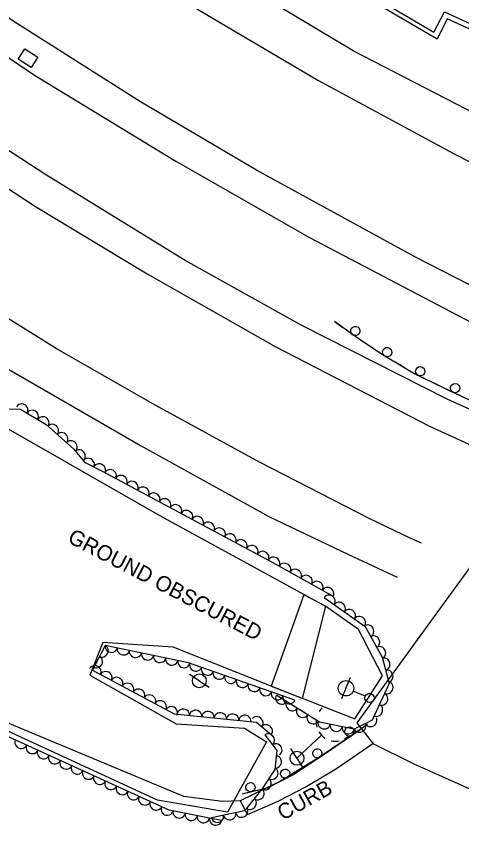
# Model space of a CAD drawing. Extents: x 1722896 to 1754269, y 648279 to 666297.
# Drawn here: x 1732619.2 to 1732763.3, y 649899.6 to 650161.6 of the extents above; entities that cross this region are included whole.
import ezdxf

# ---------------------------------------------------------------- set-up
doc = ezdxf.new("R2010")
doc.units = 0
for name, color, linetype in [('DESIGN - CENTERLINE - Proposed', 7, 'Continuous'), ('DESIGN - SCRATCH - User 1', 7, 'Continuous'), ('SURVEY - CENTERLINE - Preliminary', 7, 'Continuous'), ('SURVEY - CENTERLINE - Preliminary Text', 7, 'Continuous'), ('SURVEY - DRAINAGE - Natural Features', 7, 'Continuous'), ('SURVEY - DTM - Breaklines', 7, 'Continuous'), ('SURVEY - VEGETATION - Features with Text', 7, 'Continuous')]:
    doc.layers.add(name, color=color, linetype=linetype)

msp = doc.modelspace()

# ---------------------------------------------------------------- linework, layer by layer
at = {"layer": 'DESIGN - CENTERLINE - Proposed'}
msp.add_lwpolyline([(1732862.56, 650114.58), (1732871.81, 650112.14), (1732902.49, 650099), (1732911.38, 650094.61), (1732875.47, 650043.75), (1732812.6, 649955.84), (1732779.3, 649905.53), (1732747.93, 649919.55), (1732734.8, 649926.01), (1732729.4, 649932.93), (1732767.07, 649984.71), (1732812.61, 650049.09), (1732862.37, 650114.64)], dxfattribs=at)
at = {"layer": 'DESIGN - SCRATCH - User 1'}
for points in [[(1732834.68, 650126), (1732758.54, 650160.8), (1732755.35, 650154.19), (1732710.88, 650180.25), (1732670.33, 650204.01), (1732631.97, 650229.97), (1732581.97, 650266.2), (1732540.95, 650298.38), (1732462.37, 650368.7), (1732410.9, 650421.21), (1732341.07, 650504.92), (1732282.07, 650581.96), (1732214.97, 650674.59)], [(1732228.27, 650658.35), (1732269.62, 650601.48), (1732317.04, 650538.22), (1732364.61, 650478.14), (1732411.75, 650421.99), (1732463.83, 650368.65), (1732537.95, 650302.48), (1732586.89, 650264.11), (1732641.63, 650224.65), (1732675.82, 650201.62), (1732721.34, 650175.88), (1732754.2, 650156.42), (1732757.74, 650162.98), (1732807.66, 650139.97)], [(1732722.9, 650062.2), (1732722.08, 650062.78)], [(1732761.38, 650039.45), (1732747.6, 650046.14), (1732737.29, 650052.27), (1732729.73, 650057.27), (1732722.08, 650062.78)], [(1732724.8, 650060.82), (1732722.9, 650062.2)], [(1732729.83, 650057.2), (1732729.73, 650057.27), (1732726.1, 650059.89)], [(1732733.13, 650055.03), (1732731.17, 650056.32)], [(1732735.09, 650053.73), (1732733.13, 650055.03)], [(1732740.35, 650050.45), (1732737.29, 650052.27), (1732736.43, 650052.85)], [(1732743.75, 650048.43), (1732741.73, 650049.63)], [(1732745.77, 650047.23), (1732743.75, 650048.43)], [(1732751.26, 650044.36), (1732747.6, 650046.14), (1732747.14, 650046.41)], [(1732754.81, 650042.64), (1732752.7, 650043.66)], [(1732756.92, 650041.61), (1732754.81, 650042.64)], [(1732762.51, 650038.93), (1732761.38, 650039.45), (1732758.36, 650040.91)], [(1732777.47, 650032.08), (1732761.38, 650039.45)], [(1732732.83, 649932.49), (1732727.89, 649928.97), (1732718.79, 649922.75), (1732708.95, 649916.23), (1732700.34, 649911.85), (1732692.24, 649909.9)], [(1732729.61, 649930.2), (1732727.89, 649928.97), (1732725.84, 649927.57)], [(1732732.83, 649932.49), (1732730.91, 649931.12)], [(1732722.58, 649925.34), (1732720.64, 649924.01)], [(1732724.52, 649926.66), (1732722.58, 649925.34)], [(1732719.32, 649923.11), (1732718.79, 649922.75), (1732715.49, 649920.56)], [(1732714.15, 649919.68), (1732712.19, 649918.38)], [(1732712.19, 649918.38), (1732710.23, 649917.08)], [(1732708.9, 649916.2), (1732704.8, 649914.12)], [(1732701.28, 649912.33), (1732700.34, 649911.85), (1732699.08, 649911.55)], [(1732703.37, 649913.39), (1732701.28, 649912.33)], [(1732697.52, 649911.17), (1732693.05, 649910.1)]]:
    msp.add_lwpolyline(points, dxfattribs=at)
for centre, start, end in [((1732728.86, 650059.75), 347.4871, 347.4773), ((1732739.16, 650052.91), 352.4968, 352.4869), ((1732749.86, 650046.71), 357.3719, 357.3621), ((1732761.11, 650041.25), 357.3719, 357.3621), ((1732726.91, 649930.12), 57.637, 57.6272), ((1732716.59, 649923.09), 56.7664, 56.7566), ((1732706.19, 649916.51), 50.2371, 50.2273), ((1732694.95, 649912.1), 36.7851, 36.7753)]:
    msp.add_arc(centre, 1.5, start, end, dxfattribs=at)
at = {"layer": 'SURVEY - CENTERLINE - Preliminary'}
for points in [[(1732606.63, 650033.74), (1732665.91, 649999.81), (1732719.2, 649970.67), (1732711.67, 649940.84), (1732669.93, 649957.43), (1732647.19, 649958.96), (1732643.03, 649948.34), (1732670.93, 649932.64), (1732692.98, 649931.22), (1732700.1, 649926.85), (1732687.52, 649904), (1732664.85, 649907.92), (1732605.14, 649935.45)], [(1732701.67, 649944.83), (1732711.71, 649940.93), (1732728.7, 649934.26), (1732737.67, 649948.2), (1732729.86, 649963.14), (1732719.2, 649970.67), (1732712.16, 649974.42), (1732701.67, 649944.83)]]:
    msp.add_lwpolyline(points, dxfattribs=at)
at = {"layer": 'SURVEY - CENTERLINE - Preliminary Text'}
for points in [[(1732177.23, 650670.78), (1732207.28, 650628.76), (1732240.27, 650584.01), (1732277.17, 650534.26), (1732308.17, 650494.8), (1732347.59, 650447.31), (1732385.2, 650405.27), (1732423.32, 650365.2), (1732455.21, 650333.82), (1732493.46, 650299.04), (1732525.54, 650271.93), (1732567.3, 650239.43), (1732600.18, 650214.95), (1732636.27, 650190.54), (1732676.54, 650164.63), (1732716.69, 650140.93), (1732760.83, 650117.07), (1732799.05, 650097.55)], [(1732778.62, 650068.08), (1732748.36, 650083.69), (1732696.91, 650111.79), (1732659.43, 650133.9), (1732618.71, 650159.74), (1732569.4, 650193.82), (1732523.94, 650227.88), (1732487.08, 650258.27), (1732439.71, 650299.95), (1732393.89, 650344.9), (1732345.63, 650396.27), (1732315.87, 650430.1), (1732281.7, 650470.92), (1732248.95, 650512.82), (1732219.45, 650552.09), (1732190.79, 650591.17), (1732151.27, 650646.44)], [(1732143.79, 650639.34), (1732153.13, 650625.88), (1732193.64, 650569.45), (1732232.08, 650517.33), (1732271.5, 650466.99), (1732311.93, 650418.7), (1732362.13, 650362.86), (1732398.54, 650325.18), (1732431.93, 650292.77), (1732461.34, 650265.94), (1732489.99, 650242.08), (1732529.79, 650210.06), (1732579.85, 650173.43), (1732625.15, 650142.57), (1732670.82, 650114.68), (1732714.02, 650089.97), (1732772.83, 650059.19)], [(1732758.57, 650037.66), (1732711.61, 650061.49), (1732673.88, 650082.51), (1732628.45, 650110.48), (1732577.41, 650143.72), (1732530.35, 650177.49), (1732484.46, 650213.66), (1732441.73, 650249.76), (1732398.13, 650290.47), (1732360.12, 650328.45), (1732319.14, 650371.25), (1732281.23, 650415.01), (1732242.63, 650463.01), (1732208.97, 650506.59), (1732169.3, 650559.09), (1732132.45, 650611.35), (1732124.72, 650622.47)], [(1732116.77, 650615.12), (1732154.56, 650561.87), (1732197.78, 650503.43), (1732240.48, 650448.7), (1732279.53, 650400.92), (1732304.66, 650372.14), (1732330.13, 650344.56), (1732363.24, 650310.31), (1732395.54, 650278.52), (1732428.24, 650247.68), (1732459.96, 650219.74), (1732492.98, 650192.82), (1732520.72, 650171.8), (1732555.83, 650146.42), (1732590.52, 650122.88), (1732625.42, 650100.02), (1732661.59, 650078.24), (1732702.96, 650054.7), (1732752.88, 650028.99)], [(1732733.54, 649998.91), (1732697.9, 650017.32), (1732664.31, 650035.65), (1732632.41, 650053.89), (1732595.91, 650076.67), (1732547.12, 650109.2), (1732508.27, 650137.06), (1732471.36, 650165.08), (1732438.09, 650192.32), (1732405.65, 650220.47), (1732374.22, 650249.28), (1732344.15, 650278.5), (1732307.7, 650316.31), (1732271.64, 650356.22), (1732236.11, 650397.76), (1732206.87, 650433.94), (1732165.04, 650487.7), (1732127.45, 650538.61), (1732090.56, 650590.36)], [(1732806.82, 650109.94), (1732774.68, 650126.31), (1732728.14, 650150.41), (1732672.63, 650183.75), (1732665.95, 650187.72), (1732663.45, 650204.54)], [(1732568.66, 650060.45), (1732571.05, 650063.25), (1732581.78, 650066.81), (1732584.49, 650067.7), (1732616.43, 650047.5), (1732659.33, 650022.69), (1732700.84, 649999.68), (1732726.62, 649987.38)], [(1732775.76, 650029.94), (1732758.57, 650037.66)], [(1732752.88, 650028.99), (1732770.29, 650021.01)], [(1732750.21, 649991.09), (1732746.62, 649992.68), (1732733.54, 649998.91)], [(1732685.83, 649907.52), (1732673.4, 649909.09), (1732614.59, 649933.71), (1732561.2, 649957.23), (1732486.83, 649986.86)], [(1732726.62, 649987.38), (1732742.4, 649980.12)], [(1732730.51, 649930.74), (1732716.91, 649921.62), (1732704.67, 649914.12), (1732691.63, 649907.69), (1732694.02, 649903.26), (1732703.88, 649907.57), (1732712.68, 649912.15), (1732722.79, 649918.18), (1732734.5, 649926.24)], [(1732691.63, 649907.69), (1732685.83, 649907.52)]]:
    msp.add_lwpolyline(points, dxfattribs=at)
at = {"layer": 'SURVEY - DRAINAGE - Natural Features'}
msp.add_line((1732623.03, 650148.06), (1732623.03, 650148.06), dxfattribs=at)
msp.add_lwpolyline([(1732619.85, 650147.72), (1732622, 650151.09), (1732626.21, 650148.4), (1732624.06, 650145.03), (1732619.85, 650147.72)], dxfattribs=at)
at = {"layer": 'SURVEY - DTM - Breaklines'}
for p, q in [((1732678.41, 649946.51), (1732675.26, 649948.54)), ((1732678.41, 649946.51), (1732681.57, 649944.49)), ((1732725.84, 649944.14), (1732727.27, 649947.61)), ((1732725.84, 649944.14), (1732724.42, 649940.67)), ((1732732.09, 649941.57), (1732728.15, 649943.19)), ((1732709.99, 649921.48), (1732717.94, 649928.97)), ((1732716.92, 649928.01), (1732717.94, 649928.97)), ((1732709.99, 649921.48), (1732708.03, 649924.67)), ((1732709.99, 649921.48), (1732711.96, 649918.28))]:
    msp.add_line(p, q, dxfattribs=at)
for centre, radius in [((1732678.41, 649946.51), 2.25), ((1732725.84, 649944.14), 2.5), ((1732733.47, 649941), 1.5), ((1732709.99, 649921.48), 2.25)]:
    msp.add_circle(centre, radius, dxfattribs=at)
for start, end in [(133.3124, 147.9332), (175.1902, 195.5328), (210.8333, 237.3486), (298.4989, 312.3883), (256.8751, 281.6452)]:
    msp.add_arc((1732722.42, 649933.26), 6.25, start, end, dxfattribs=at)
at = {"layer": 'SURVEY - VEGETATION - Features with Text'}
for points in [[(1732208.88, 650390.07), (1732234.44, 650360.27), (1732291.89, 650295.69), (1732323.22, 650261.3), (1732333.06, 650261.67), (1732340.1, 650256.13), (1732343.56, 650248.69), (1732349.55, 650240.8), (1732361.45, 650233.68), (1732371.73, 650224.61), (1732381.58, 650215.44), (1732394.17, 650202.11), (1732432.99, 650162.24), (1732489.1, 650117.33), (1732559.6, 650068.42), (1732612.95, 650034.59), (1732620.61, 650034.45), (1732628.88, 650029.49), (1732637.82, 650021.54), (1732641.29, 650017.29), (1732647.22, 650014.29), (1732701.95, 649984.95), (1732721.45, 649974.04)], [(1732685.62, 649901.29), (1732668.61, 649904.65), (1732601.93, 649935.11), (1732613.35, 649955.63), (1732584.55, 649974.3), (1732579.36, 649968.37), (1732575.9, 649949.95), (1732526.12, 649974.89), (1732518.51, 650008.11), (1732494.93, 650021.3), (1732464.7, 650057.84), (1732451.25, 650069.32), (1732451.51, 650058.78), (1732461.96, 650046.79), (1732458.07, 650028.37), (1732483.19, 650013.03), (1732492, 649999.88), (1732483.27, 649989.84)], [(1732718.77, 649973.49), (1732732.09, 649964.17), (1732737.59, 649954.16), (1732739.8, 649945.63), (1732734.33, 649933.84), (1732728.46, 649930.85), (1732717.32, 649933.14), (1732703.48, 649941.83)], [(1732709.34, 649940.32), (1732674.93, 649952.36), (1732648, 649958.02), (1732643.81, 649950.03), (1732670.26, 649935.85), (1732696.93, 649933.15), (1732702.47, 649928.42)], [(1732699.63, 649929.02), (1732703.44, 649923.95), (1732702.82, 649917.89), (1732698.65, 649911.52), (1732693.03, 649904.47), (1732682.36, 649902.17)]]:
    msp.add_lwpolyline(points, dxfattribs=at)
for centre, major_axis in [((1732621, 650034.22), (1.72, -1.03)), ((1732624.43, 650032.16), (1.72, -1.03)), ((1732627.86, 650030.1), (1.72, -1.03)), ((1732630.98, 650027.62), (1.49, -1.33)), ((1732633.97, 650024.96), (1.49, -1.33)), ((1732636.96, 650022.3), (1.49, -1.33)), ((1732639.62, 650019.33), (1.26, -1.55)), ((1732642.5, 650016.67), (1.79, -0.9)), ((1732646.07, 650014.87), (1.79, -0.9)), ((1732649.61, 650013.01), (1.76, -0.94)), ((1732653.14, 650011.12), (1.76, -0.94)), ((1732656.67, 650009.23), (1.76, -0.94)), ((1732660.19, 650007.34), (1.76, -0.94)), ((1732663.72, 650005.45), (1.76, -0.94)), ((1732667.24, 650003.56), (1.76, -0.94)), ((1732670.77, 650001.67), (1.76, -0.94)), ((1732674.29, 649999.78), (1.76, -0.94)), ((1732677.82, 649997.89), (1.76, -0.94)), ((1732681.34, 649996), (1.76, -0.94)), ((1732684.87, 649994.11), (1.76, -0.94)), ((1732688.39, 649992.22), (1.76, -0.94)), ((1732691.92, 649990.33), (1.76, -0.94)), ((1732695.44, 649988.44), (1.76, -0.94)), ((1732698.97, 649986.55), (1.76, -0.94)), ((1732702.49, 649984.65), (1.75, -0.98)), ((1732705.98, 649982.7), (1.75, -0.98)), ((1732709.47, 649980.74), (1.75, -0.98)), ((1732712.96, 649978.79), (1.75, -0.98)), ((1732716.45, 649976.84), (1.75, -0.98)), ((1732719.94, 649974.88), (1.75, -0.98)), ((1732720.4, 649972.35), (1.64, -1.15)), ((1732723.68, 649970.05), (1.64, -1.15)), ((1732726.96, 649967.76), (1.64, -1.15)), ((1732730.23, 649965.46), (1.64, -1.15)), ((1732732.93, 649962.64), (0.96, -1.75)), ((1732734.85, 649959.14), (0.96, -1.75)), ((1732647.06, 649956.22), (-0.93, -1.77)), ((1732649.93, 649957.61), (-1.96, 0.41)), ((1732653.84, 649956.79), (-1.96, 0.41)), ((1732657.76, 649955.97), (-1.96, 0.41)), ((1732736.78, 649955.63), (0.96, -1.75)), ((1732645.2, 649952.68), (-0.93, -1.77)), ((1732661.67, 649955.15), (-1.96, 0.41)), ((1732665.59, 649954.33), (-1.96, 0.41)), ((1732669.5, 649953.5), (-1.96, 0.41)), ((1732738.17, 649951.92), (0.5, -1.94)), ((1732644.7, 649949.55), (1.76, -0.94)), ((1732673.42, 649952.68), (-1.96, 0.41)), ((1732677.24, 649951.55), (-1.89, 0.66)), ((1732648.23, 649947.66), (1.76, -0.94)), ((1732681.02, 649950.23), (-1.89, 0.66)), ((1732684.8, 649948.91), (-1.89, 0.66)), ((1732739.17, 649948.04), (0.5, -1.94)), ((1732651.75, 649945.77), (1.76, -0.94)), ((1732655.28, 649943.88), (1.76, -0.94)), ((1732688.57, 649947.59), (-1.89, 0.66)), ((1732692.35, 649946.27), (-1.89, 0.66)), ((1732739.17, 649944.26), (-0.84, -1.81)), ((1732658.8, 649941.99), (1.76, -0.94)), ((1732696.12, 649944.95), (-1.89, 0.66)), ((1732699.9, 649943.62), (-1.89, 0.66)), ((1732662.33, 649940.1), (1.76, -0.94)), ((1732703.67, 649942.3), (-1.89, 0.66)), ((1732705, 649940.87), (-1.69, 1.06)), ((1732707.45, 649940.98), (-1.89, 0.66)), ((1732737.48, 649940.63), (-0.84, -1.81)), ((1732665.85, 649938.21), (1.76, -0.94)), ((1732669.38, 649936.32), (1.76, -0.94)), ((1732708.39, 649938.75), (-1.69, 1.06)), ((1732735.8, 649937.01), (-0.84, -1.81)), ((1732673.24, 649935.55), (1.99, -0.2)), ((1732677.22, 649935.14), (1.99, -0.2)), ((1732681.2, 649934.74), (1.99, -0.2)), ((1732685.18, 649934.34), (1.99, -0.2)), ((1732689.16, 649933.93), (1.99, -0.2)), ((1732693.14, 649933.53), (1.99, -0.2)), ((1732711.78, 649936.62), (-1.69, 1.06)), ((1732715.16, 649934.49), (-1.69, 1.06)), ((1732697.08, 649933.02), (1.52, -1.3)), ((1732718.74, 649932.85), (-1.96, 0.4)), ((1732733.88, 649933.61), (-1.78, -0.91)), ((1732700.12, 649930.42), (1.52, -1.3)), ((1732722.66, 649932.04), (-1.96, 0.4)), ((1732726.58, 649931.24), (-1.96, 0.4)), ((1732730.32, 649931.79), (-1.78, -0.91)), ((1732700.83, 649927.42), (1.2, -1.6)), ((1732620.71, 649926.54), (-1.82, 0.83)), ((1732624.34, 649924.87), (-1.82, 0.83)), ((1732703.24, 649924.22), (1.2, -1.6)), ((1732627.98, 649923.21), (-1.82, 0.83)), ((1732631.62, 649921.55), (-1.82, 0.83)), ((1732703.07, 649920.31), (-0.2, -1.99)), ((1732635.26, 649919.89), (-1.82, 0.83)), ((1732638.9, 649918.22), (-1.82, 0.83)), ((1732642.54, 649916.56), (-1.82, 0.83)), ((1732701.96, 649916.58), (-1.1, -1.67)), ((1732646.17, 649914.9), (-1.82, 0.83)), ((1732699.77, 649913.23), (-1.1, -1.67)), ((1732649.81, 649913.24), (-1.82, 0.83)), ((1732653.45, 649911.58), (-1.82, 0.83)), ((1732657.09, 649909.91), (-1.82, 0.83)), ((1732697.43, 649910), (-1.25, -1.56)), ((1732660.73, 649908.25), (-1.82, 0.83)), ((1732664.37, 649906.59), (-1.82, 0.83)), ((1732694.94, 649906.87), (-1.25, -1.56)), ((1732668, 649904.93), (-1.82, 0.83)), ((1732671.88, 649904), (-1.96, 0.39)), ((1732692.11, 649904.27), (-1.95, -0.42)), ((1732675.81, 649903.23), (-1.96, 0.39)), ((1732679.73, 649902.46), (-1.96, 0.39)), ((1732683.65, 649901.68), (-1.96, 0.39)), ((1732684.29, 649902.59), (-1.95, -0.42)), ((1732688.2, 649903.43), (-1.95, -0.42))]:
    msp.add_ellipse(centre, major_axis=major_axis, ratio=0.940188, start_param=0, end_param=3.141593, dxfattribs=at)

# ---------------------------------------------------------------- texts
at = {"layer": 'DESIGN - SCRATCH - User 1'}
msp.add_text('CURB', height=5, rotation=29.1115, dxfattribs=at).set_placement((1732705.39, 649901.21))
at = {"layer": 'SURVEY - CENTERLINE - Preliminary'}
msp.add_text('GROUND OBSCURED', height=5, rotation=332.3433, dxfattribs=at).set_placement((1732635.47, 649991.58))

doc.saveas('drawing.dxf')
